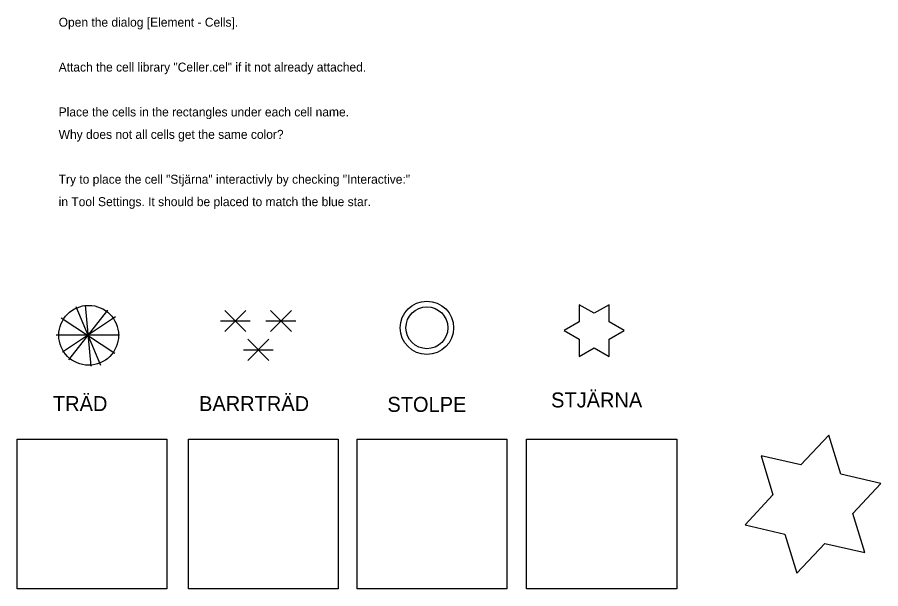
# Model space of a CAD drawing. Extents: x 1517699.5 to 1517728.4, y 6495354.2 to 6495373.3.
import ezdxf

# ---------------------------------------------------------------- set-up
doc = ezdxf.new("R2010")
doc.units = 0
doc.layers.add('Instruktioner', color=7, linetype='Continuous')
doc.layers.add('Lager 1', color=7, linetype='Continuous')

msp = doc.modelspace()

# ---------------------------------------------------------------- linework, layer by layer
at = {"layer": 'Instruktioner'}
for p, q in [((1517706.471, 6495362.824), (1517707.178, 6495363.531)), ((1517707.178, 6495362.824), (1517706.471, 6495363.531)), ((1517707.995, 6495362.824), (1517708.702, 6495363.531)), ((1517708.702, 6495362.824), (1517707.995, 6495363.531)), ((1517706.325, 6495363.178), (1517707.325, 6495363.178)), ((1517707.848, 6495363.178), (1517708.848, 6495363.178)), ((1517707.24, 6495361.858), (1517707.947, 6495362.565)), ((1517707.947, 6495361.858), (1517707.24, 6495362.565)), ((1517707.094, 6495362.211), (1517708.094, 6495362.211))]:
    msp.add_line(p, q, dxfattribs=at)
for points in [[(1517699.539, 6495359.224), (1517704.539, 6495359.224), (1517704.539, 6495354.224), (1517699.539, 6495354.224)], [(1517705.265, 6495359.224), (1517710.265, 6495359.224), (1517710.265, 6495354.224), (1517705.265, 6495354.224)], [(1517710.9, 6495359.224), (1517715.9, 6495359.224), (1517715.9, 6495354.224), (1517710.9, 6495354.224)], [(1517716.556, 6495359.224), (1517721.58, 6495359.224), (1517721.58, 6495354.224), (1517716.556, 6495354.224)]]:
    msp.add_lwpolyline(points, close=True, dxfattribs=at)
at = {"layer": 'Lager 1'}
for p, q in [((1517702.558, 6495363.539), (1517701.255, 6495361.873)), ((1517701.493, 6495363.661), (1517702.325, 6495361.696)), ((1517701.807, 6495363.705), (1517701.997, 6495361.661)), ((1517701.005, 6495363.286), (1517702.803, 6495362.105)), ((1517702.818, 6495363.31), (1517701.052, 6495362.132)), ((1517702.953, 6495362.698), (1517700.843, 6495362.698))]:
    msp.add_line(p, q, dxfattribs=at)
for points in [[(1517719.311, 6495363.72), (1517718.811, 6495363.434), (1517718.311, 6495363.72), (1517718.309, 6495363.144), (1517717.811, 6495362.854), (1517718.309, 6495362.564), (1517718.311, 6495361.988), (1517718.811, 6495362.274), (1517719.311, 6495361.988), (1517719.313, 6495362.564), (1517719.811, 6495362.854), (1517719.313, 6495363.144)], [(1517726.658, 6495359.357), (1517725.722, 6495358.364), (1517724.392, 6495358.668), (1517724.784, 6495357.361), (1517723.855, 6495356.361), (1517725.183, 6495356.047), (1517725.585, 6495354.743), (1517726.521, 6495355.736), (1517727.852, 6495355.432), (1517727.459, 6495356.739), (1517728.388, 6495357.739), (1517727.06, 6495358.053)]]:
    msp.add_lwpolyline(points, close=True, dxfattribs=at)
for centre, radius in [((1517713.225, 6495362.948), 0.891), ((1517701.924, 6495362.698), 1), ((1517713.225, 6495362.948), 0.7)]:
    msp.add_circle(centre, radius, dxfattribs=at)

# ---------------------------------------------------------------- texts
at = {"layer": 'Instruktioner'}
for s, height, p in [('Open the dialog [Element - Cells].', 0.3, (1517700.922, 6495373.015)), ('Attach the cell library "Celler.cel" if it not already attached.', 0.3, (1517700.922, 6495371.515)), ('Place the cells in the rectangles under each cell name.', 0.3, (1517700.922, 6495370.015)), ('Why does not all cells get the same color?', 0.3, (1517700.922, 6495369.265)), ('Try to place the cell "Stjärna" interactivly by checking "Interactive:"', 0.3, (1517700.922, 6495367.765)), ('in Tool Settings. It should be placed to match the blue star.', 0.3, (1517700.922, 6495367.015)), ('STJÄRNA', 0.5, (1517717.374, 6495360.285)), ('TRÄD', 0.5, (1517700.73, 6495360.164)), ('BARRTRÄD', 0.5, (1517705.612, 6495360.164)), ('STOLPE', 0.5, (1517711.905, 6495360.138))]:
    msp.add_text(s, height=height, dxfattribs=at).set_placement(p)

doc.saveas('drawing.dxf')
